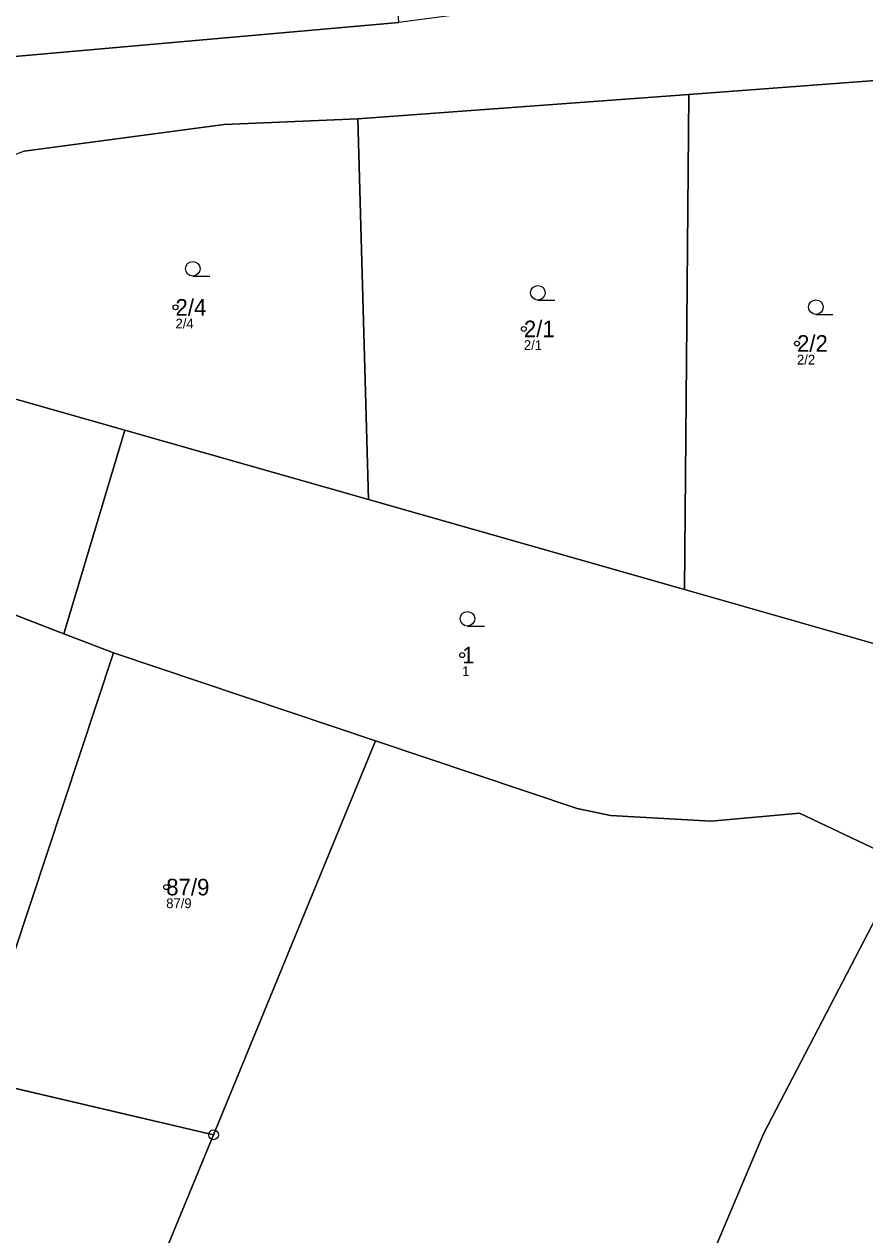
# Model space of a CAD drawing. Extents: x -767985 to -763816, y -1059600 to -1057360.
# Drawn here: x -765772.9 to -765686.8, y -1058679.6 to -1058555.6 of the extents above; entities that cross this region are included whole.
import ezdxf

# ---------------------------------------------------------------- set-up
doc = ezdxf.new("R2010")
doc.units = 0
for name, color, linetype in [('Definiční body', 7, 'Continuous'), ('Hranice parcel', 7, 'Continuous'), ('Parcelní čísla', 7, 'Continuous'), ('Polygon parcely', 7, 'Continuous'), ('Značky bodu BP', 7, 'Continuous'), ('Značky kultur', 7, 'Continuous')]:
    doc.layers.add(name, color=color, linetype=linetype)

msp = doc.modelspace()

# ---------------------------------------------------------------- linework, layer by layer
at = {"layer": 'Definiční body'}
for centre in [(-765757.4, -1058584.56994), (-765721.71, -1058586.77994), (-765693.73, -1058588.26994), (-765728.03, -1058620.19994), (-765758.35, -1058643.96994)]:
    msp.add_circle(centre, 0.25, dxfattribs=at)
at = {"layer": 'Hranice parcel'}
for p, q in [((-765680.69, -1058560.96), (-765704.8, -1058562.77)), ((-765704.8, -1058562.77), (-765738.71, -1058565.26)), ((-765705.24, -1058613.48), (-765704.8, -1058562.77)), ((-765738.71, -1058565.26), (-765737.64, -1058604.27)), ((-765768.85, -1058618.01), (-765762.6, -1058597.16)), ((-765737.64, -1058604.27), (-765762.6, -1058597.16)), ((-765705.24, -1058613.48), (-765737.64, -1058604.27)), ((-765793.11, -1058608.61), (-765768.85, -1058618.01)), ((-765680.64, -1058620.52), (-765705.24, -1058613.48)), ((-765768.85, -1058618.01), (-765763.76, -1058619.98)), ((-765763.76, -1058619.98), (-765736.9, -1058628.99)), ((-765753.5, -1058669.35), (-765736.9, -1058628.99)), ((-765753.5, -1058669.35), (-765810.12, -1058656.11))]:
    msp.add_line(p, q, dxfattribs=at)
for points in [[(-765734.53, -1058555.37), (-765790.13, -1058560.29), (-765835.08, -1058560.96), (-765864.89, -1058547.27), (-765897.47, -1058520.44), (-765902.49, -1058514.97)], [(-765738.71, -1058565.26), (-765752.4, -1058565.82), (-765772.9, -1058568.58), (-765777.38, -1058570.3)], [(-765762.6, -1058597.16), (-765780.28, -1058592.12), (-765787.03, -1058590.31)], [(-765807.84, -1058648.45), (-765775.69, -1058655.96), (-765763.76, -1058619.98)], [(-765736.9, -1058628.99), (-765716.24, -1058635.92), (-765712.82, -1058636.63), (-765702.54, -1058637.22), (-765693.49, -1058636.4), (-765684.83, -1058640.48)], [(-765683.03, -1058642.09), (-765697.17, -1058669.25), (-765714.24, -1058709.63)], [(-765806.73, -1058810.83), (-765758.72, -1058682.04), (-765753.5, -1058669.35)]]:
    msp.add_lwpolyline(points, dxfattribs=at)
at = {"layer": 'Polygon parcely'}
for points in [[(-765790.13, -1058560.29), (-765734.53, -1058555.37), (-765735.06, -1058546.22), (-765735.14, -1058532.31), (-765735.14, -1058520.7), (-765737.79, -1058520.7), (-765737.79, -1058509.74), (-765737.79, -1058503.29), (-765735.2, -1058502.21), (-765734.9, -1058463.64), (-765702.26, -1058466.55), (-765679.14, -1058466.03), (-765660.12, -1058465.61), (-765653.83, -1058465.59), (-765654.49, -1058450.01), (-765625.29, -1058448.19), (-765604.61, -1058446.9), (-765579.41, -1058445.32), (-765580.24, -1058470.78), (-765580.34, -1058474.01), (-765575.09, -1058473.86)], [(-765563.59, -1058565.4), (-765577.41, -1058559.35), (-765610.08, -1058553.62), (-765658.68, -1058545.6), (-765681.43, -1058546.75), (-765714.08, -1058552.66), (-765734.53, -1058555.37), (-765790.13, -1058560.29)], [(-765772.9, -1058568.58), (-765752.4, -1058565.82), (-765738.71, -1058565.26), (-765704.8, -1058562.77), (-765680.69, -1058560.96), (-765664.11, -1058559.73), (-765646.01, -1058560.26), (-765626.2, -1058560.85), (-765610.51, -1058559.8), (-765610.51, -1058559.05), (-765605.36, -1058558), (-765599.74, -1058557.65)]]:
    msp.add_lwpolyline(points, dxfattribs=at)
for points in [[(-765680.64, -1058620.52), (-765680.69, -1058560.96), (-765704.8, -1058562.77), (-765705.24, -1058613.48)], [(-765737.64, -1058604.27), (-765705.24, -1058613.48), (-765704.8, -1058562.77), (-765738.71, -1058565.26)], [(-765777.38, -1058570.3), (-765781.09, -1058578), (-765787.03, -1058590.31), (-765780.28, -1058592.12), (-765762.6, -1058597.16), (-765737.64, -1058604.27), (-765738.71, -1058565.26), (-765752.4, -1058565.82), (-765772.9, -1058568.58)], [(-765762.6, -1058597.16), (-765780.28, -1058592.12), (-765787.03, -1058590.31), (-765793.11, -1058608.61), (-765768.85, -1058618.01)], [(-765716.24, -1058635.92), (-765712.82, -1058636.63), (-765702.54, -1058637.22), (-765693.49, -1058636.4), (-765684.83, -1058640.48), (-765678.84, -1058632.4), (-765674.02, -1058622.41), (-765680.64, -1058620.52), (-765705.24, -1058613.48), (-765737.64, -1058604.27), (-765762.6, -1058597.16), (-765768.85, -1058618.01), (-765763.76, -1058619.98), (-765736.9, -1058628.99)], [(-765793.11, -1058608.61), (-765807.84, -1058648.45), (-765775.69, -1058655.96), (-765763.76, -1058619.98), (-765768.85, -1058618.01)], [(-765753.5, -1058669.35), (-765736.9, -1058628.99), (-765763.76, -1058619.98), (-765775.69, -1058655.96), (-765807.84, -1058648.45), (-765810.12, -1058656.11)], [(-765782.47, -1058819.11), (-765770.1, -1058822.41), (-765724.24, -1058705.36), (-765714.24, -1058709.63), (-765697.17, -1058669.25), (-765683.03, -1058642.09), (-765684.2, -1058641.13), (-765684.83, -1058640.48), (-765693.49, -1058636.4), (-765702.54, -1058637.22), (-765712.82, -1058636.63), (-765716.24, -1058635.92), (-765736.9, -1058628.99), (-765753.5, -1058669.35), (-765758.72, -1058682.04), (-765806.73, -1058810.83)], [(-765697.17, -1058669.25), (-765714.24, -1058709.63), (-765715.05, -1058711.54), (-765680.11, -1058729.21), (-765666.71, -1058698.67), (-765659.24, -1058676.64), (-765657.24, -1058670.64), (-765656.5, -1058668.42), (-765657.66, -1058662.64), (-765666.36, -1058655.89), (-765683.03, -1058642.09)], [(-765810.12, -1058656.11), (-765815.49, -1058674.19), (-765857.62, -1058793.46), (-765806.73, -1058810.83), (-765758.72, -1058682.04), (-765753.5, -1058669.35)]]:
    msp.add_lwpolyline(points, close=True, dxfattribs=at)
at = {"layer": 'Značky bodu BP'}
for radius in [0.5, 0.0303]:
    msp.add_circle((-765753.5, -1058669.34988), radius, dxfattribs=at)
at = {"layer": 'Značky kultur'}
for p, q in [((-765755.633, -1058581.37), (-765753.883, -1058581.37)), ((-765720.273, -1058583.83), (-765718.523, -1058583.83)), ((-765691.793, -1058585.3), (-765690.043, -1058585.3)), ((-765727.493, -1058617.23), (-765725.743, -1058617.23))]:
    msp.add_line(p, q, dxfattribs=at)
for centre in [(-765755.63286, -1058580.61981), (-765720.27286, -1058583.07981), (-765691.79286, -1058584.54981), (-765727.49286, -1058616.47981)]:
    msp.add_circle(centre, 0.75, dxfattribs=at)

# ---------------------------------------------------------------- texts
at = {"layer": 'Definiční body'}
for s, height, p in [('2/4', 0.999996, (-765757.4, -1058586.726)), ('2/1', 0.999996, (-765721.71, -1058588.936)), ('2/2', 0.999996, (-765693.73, -1058590.426)), ('1', 1, (-765728.03, -1058622.356)), ('87/9', 0.999996, (-765758.35, -1058646.126))]:
    msp.add_text(s, height=height, dxfattribs=at).set_placement(p)
at = {"layer": 'Parcelní čísla'}
for s, height, p in [('2/4', 1.699998, (-765757.4, -1058585.42)), ('2/1', 1.699998, (-765721.71, -1058587.63)), ('2/2', 1.699998, (-765693.73, -1058589.12)), ('1', 1.7, (-765728.03, -1058621.05)), ('87/9', 1.699998, (-765758.35, -1058644.82))]:
    msp.add_text(s, height=height, dxfattribs=at).set_placement(p)

doc.saveas('drawing.dxf')
